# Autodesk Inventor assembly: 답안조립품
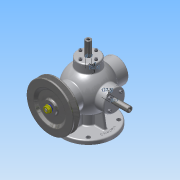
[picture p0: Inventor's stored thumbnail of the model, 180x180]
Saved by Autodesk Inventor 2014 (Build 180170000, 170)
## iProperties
Created: 2016-01
Part Number: 답안조립품
Document SubType Name: Assembly
Designer: Administrator
Mass: 3734.97 g
Surface Area: 2411.02 cm^2
Volume: 903.658 cm^3
Density: 4.13317 g/cm^3
Author: Administrator
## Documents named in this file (17)
- C:\Users\Administrator\Desktop\360108V1003\답안조립품.iam
- C:\Users\Administrator\Desktop\360108V1003\본체.ipt
- C:\Users\Administrator\Desktop\360108V1003\V-벨트풀리.ipt
- C:\Users\Administrator\Desktop\360108V1003\너트-M8x1.ipt
- C:\Users\Administrator\Desktop\360108V1003\뒤커버.ipt
- C:\Users\Administrator\Desktop\360108V1003\베어링- 6202.ipt
- C:\Users\Administrator\Desktop\360108V1003\본체커버.ipt
- C:\Users\Administrator\Desktop\360108V1003\볼트 M4x0.7.ipt
- C:\Users\Administrator\Desktop\360108V1003\슬라이드 커버.ipt
- C:\Users\Administrator\Desktop\360108V1003\슬라이드.ipt
- C:\Users\Administrator\Desktop\360108V1003\앞커버.ipt
- C:\Users\Administrator\Desktop\360108V1003\오일실.ipt
- C:\Users\Administrator\Desktop\360108V1003\와셔 8x17.ipt
- C:\Users\Administrator\Desktop\360108V1003\축.ipt
- C:\Users\Administrator\Desktop\360108V1003\키-4x4.ipt
- C:\Users\Administrator\Desktop\360108V1003\15-스프링.ipt
- C:\Users\Administrator\Desktop\360108V1003\16-스프링.ipt
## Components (20 placed, 4 different names)
1. V-벨트풀리:1 — 플러쉬:21, 각도:2
2. M4x0.7x12:1
3. M4x0.7x12:2
4. M4x0.7x12:3
5. M4x0.7x12:4
6. M4x0.7x12:5
7. M4x0.7x12:6
8. M4x0.7x12:7
9. M4x0.7x12:8
10. M4x0.7x12:9
11. M4x0.7x12:10
12. M4x0.7x12:11
13. M4x0.7x12:12
14. M4x0.7x12:13
15. M4x0.7x12:14
16. M4x0.7x12:15
17. M4x0.7x12:16
18. M4x0.7x12:17
19. 15-스프링:1
20. 16-스프링:1
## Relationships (2: Flush 1, Angle 1)
- 플러쉬:21 [Flush]: V-벨트풀리:1
- 각도:2 [Angle]: V-벨트풀리:1
